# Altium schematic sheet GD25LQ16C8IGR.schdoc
size 127 x 101 mm
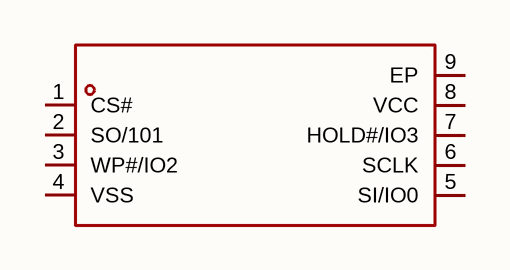
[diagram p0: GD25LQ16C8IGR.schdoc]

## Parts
U?  gd25lq16c8igr  [LGA-8_L3.0-W2.0-P0.50-TL-EP]  (value not drawn)

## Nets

Not connected (* = marked no-connect by the designer): U? 1(CS#) 2(SO/101) 3(WP#/IO2) 4(VSS) 5(SI/IO0) 6(SCLK) 7(HOLD#/IO3) 8(VCC) 9(EP)

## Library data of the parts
U? = gd25lq16c8igr: 接口类型:SPI;存储容量:16Mbit;时钟频率(fc):104MHz;; Manufacturer: GigaDevice(兆易创新); AddInBom: yes; ModelId: e1530c6879374ee892b76f3e18f4f6dd; ModelName: LGA-8_L3.0-W2.0-H0.4-P0.50-TL-EP; ModelTransform: 118.11,78.74,0,0,0,0,-0.002,0.002,0; Interface: SPI; Memory Size: 16Mbit; Clock Frequency: 104MHz; Voltage - Supply: 1.65V~2.1V; Standby Supply Current: 9uA; Program / Erase Cycles: 100000次; Page Programming Time (Tpp): 700us; Block Erase Time(tBE): 180ms; Data Retention - TDR (Year): 20年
